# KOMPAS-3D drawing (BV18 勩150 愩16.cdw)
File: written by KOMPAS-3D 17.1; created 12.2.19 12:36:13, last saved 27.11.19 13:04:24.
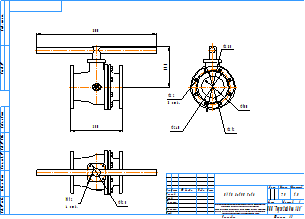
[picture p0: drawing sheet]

Sheet 1: A3, landscape

Title block, sheet 1: name: BV18 Ду150 Ру16; material: Сталь 10  ГОСТ 1050-88; mass: 75; sheets: 1; sheet format: A3; stored path: C:\Users\kka\KOMPAS_Work\!Trash\BV18\KOMPAS 2D\BV18 Ду150 Ру16.cdw

Views: Вид 1, Проекционный вид 2, Проекционный вид 3
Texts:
  kka
  adl
  Рама для чертежей
  Лит-Масса-Масштаб
  Материал-Предприятие
  Масштаб
  Изм.
  Лист
  № докум.
  Подп.
  Дата
  Лит.
  Разраб.
  Пров.
  Т.контр.
  Листов
  Внимание! Данный продукт является объектом авторского права ООО «Торговый Дом АДЛ».
  Запрещается изменение, копирование, распространение
  (в том числе путем копирования на другие сайты и ресурсы в Интернете)
  или любое иное использование информации и объектов без предварительного
  согласия правообладателя (ООО «Торговый Дом АДЛ»).
  Н.контр.
  Утв.
  ООО "Торговый дом АДЛ"
  Изменение
  Номер документа
  Подпись
  Обозначение документа
  Наименование изделия
  Масса изделия по ГОСТ 2.109-73
  Порядковый номер листа
  Общее количество листов в документе
  Характер работы, выполненной лицом, подписавшим документ
  Наименование или индекс предприятия, выпускающего документ
  Инв. № подл.
  Подп. и дата
  Взам. инв. №
  Инв. № дубл.
  Инвентарный номер подлинника по ГОСТ 2.501-68
  Подпись принявшего подлинник в отдел технической документации
  Инвентарный номер подлинника, взамен которого выпущен данный подлинник
  Инвентарный номер дубликата по ГОСТ 2.502-68
  Подпись принявшего дубликат в отдел технической документации
  Справ. №
  Перв. примен.
  Обозначение документа, взамен или на основании которого выпущен данный документ
  Обозначение документа, в котором впервые записан данный документ
  Подпись лица, копировавшего чертеж
  Обозначение формата листа
  !Рама для чертежа
Dimensions and other numbers on the sheet: 350; 270; 800; 240; 212; 22; 8 отв.; 285; 150; 125; 12; 4 отв.; 1:5; 75; 1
